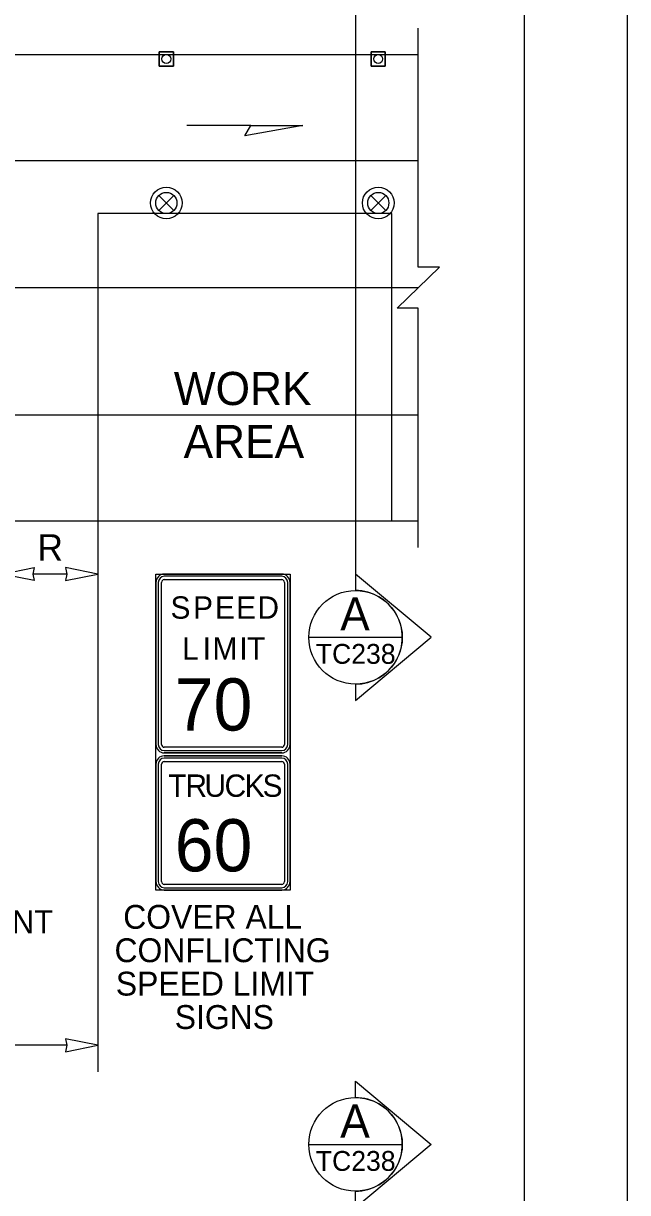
# Model space of a CAD drawing. Extents: x 99999 to 100116, y 99995 to 100013.
# Drawn here: x 100054.238 to 100056.062, y 100004.763 to 100008.293 of the extents above; entities that cross this region are included whole.
import ezdxf

# ---------------------------------------------------------------- set-up
doc = ezdxf.new("R2010")
doc.units = 0
for name, color, linetype in [('Default', 7, 'Continuous'), ('RD_MK_LineEdgeYellow', 7, 'Continuous'), ('RD_MK_LineLane', 7, 'Continuous'), ('SH_GI_PlotLimits', 7, 'Continuous'), ('SH_GI_SheetBorder', 7, 'Continuous'), ('SH_TI_WZSectionCut', 7, 'Continuous'), ('TR_SN_ConstructionSigns', 7, 'Continuous'), ('TR_WZ_TrafficCone', 7, 'Continuous'), ('TR_WZ_TrafficSafetyDrum', 7, 'Continuous'), ('TR_WZ_WorkAreaLabel', 7, 'Continuous'), ('TR_WZ_WorkZoneDetails', 7, 'Continuous'), ('TR_WZ_WorkZoneTextCurrent', 7, 'Continuous')]:
    doc.layers.add(name, color=color, linetype=linetype)

msp = doc.modelspace()

# ---------------------------------------------------------------- linework, layer by layer
at = {"layer": 'Default'}
for p, q in [((100055.0177, 100006.0819), (100054.6633, 100006.0819)), ((100054.638, 100006.0566), (100054.638, 100005.7022)), ((100055.043, 100005.7022), (100055.043, 100006.0566)), ((100054.6633, 100005.6769), (100055.0177, 100005.6769))]:
    msp.add_line(p, q, dxfattribs=at)
for centre, start, end in [((100054.6633, 100006.0566), 90, 180), ((100055.0177, 100006.0566), 0, 90), ((100054.6633, 100005.7022), 180, 270), ((100055.0177, 100005.7022), 270, 0)]:
    msp.add_arc(centre, 0.0253, start, end, dxfattribs=at)
at = {"layer": 'RD_MK_LineEdgeYellow'}
for p, q in [((100048.195, 100007.8789), (100055.43, 100007.8789)), ((100052.7368, 100007.1109), (100055.43, 100007.1109))]:
    msp.add_line(p, q, dxfattribs=at)
at = {"layer": 'RD_MK_LineLane'}
msp.add_lwpolyline([(100055.43, 100007.4949), (100048.195, 100007.4949)], dxfattribs=at)
at = {"layer": 'SH_GI_PlotLimits'}
msp.add_lwpolyline([(100039.0625, 99999.6875), (100056.0625, 99999.6875), (100056.0625, 100010.6875), (100039.0625, 100010.6875)], close=True, dxfattribs=at)
at = {"layer": 'SH_GI_SheetBorder'}
msp.add_line((100055.75, 100010.375), (100055.75, 100000), dxfattribs=at)
at = {"layer": 'SH_TI_WZSectionCut'}
for p, q in [((100055.2407, 100008.3589), (100055.2407, 100006.6309)), ((100055.2407, 100006.6309), (100055.2407, 100006.581)), ((100055.4689, 100006.4398), (100055.2407, 100006.6309)), ((100055.2407, 100006.2486), (100055.4689, 100006.4398)), ((100055.2407, 100006.2985), (100055.2407, 100006.2486)), ((100055.2407, 100005.0503), (100055.2407, 100005.1002)), ((100055.2407, 100005.1002), (100055.4688, 100004.9091)), ((100055.4688, 100004.9091), (100055.2407, 100004.718)), ((100055.2407, 100004.718), (100055.2407, 100004.7679))]:
    msp.add_line(p, q, dxfattribs=at)
for points in [[(100055.0995, 100006.4398), (100055.3819, 100006.4398)], [(100055.0995, 100004.9091), (100055.3819, 100004.9091)]]:
    msp.add_lwpolyline(points, dxfattribs=at)
for centre in [(100055.2407, 100006.4398), (100055.2407, 100004.9091)]:
    msp.add_circle(centre, 0.1412, dxfattribs=at)
for centre in [(100055.2407, 100006.4398), (100055.2407, 100004.9091)]:
    msp.add_arc(centre, 0.1412, 269.9978, 90.0022, dxfattribs=at)
at = {"layer": 'TR_SN_ConstructionSigns'}
for p, q in [((100054.638, 100006.1162), (100054.638, 100006.6056)), ((100054.638, 100006.6056), (100054.638, 100006.1162)), ((100054.6451, 100006.6056), (100054.6451, 100006.1162)), ((100054.6549, 100006.1162), (100054.6549, 100006.6056)), ((100054.6633, 100006.6309), (100055.0177, 100006.6309)), ((100055.0177, 100006.6309), (100054.6633, 100006.6309)), ((100055.0177, 100006.6239), (100054.6633, 100006.6239)), ((100054.6633, 100006.614), (100055.0177, 100006.614)), ((100055.0261, 100006.6056), (100055.0261, 100006.1162)), ((100055.036, 100006.1162), (100055.036, 100006.6056)), ((100055.043, 100006.6056), (100055.043, 100006.1162)), ((100055.043, 100006.1162), (100055.043, 100006.6056)), ((100055.0177, 100006.1078), (100054.6633, 100006.1078)), ((100054.6633, 100006.0979), (100055.0177, 100006.0979)), ((100055.0177, 100006.0909), (100054.6633, 100006.0909)), ((100054.6633, 100006.0909), (100055.0177, 100006.0909)), ((100054.6633, 100006.0819), (100055.0177, 100006.0819)), ((100055.0177, 100006.0819), (100054.6633, 100006.0819)), ((100055.0177, 100006.0749), (100054.6633, 100006.0749)), ((100054.638, 100005.7022), (100054.638, 100006.0566)), ((100054.638, 100006.0566), (100054.638, 100005.7022)), ((100054.6451, 100006.0566), (100054.6451, 100005.7022)), ((100054.6549, 100005.7022), (100054.6549, 100006.0566)), ((100054.6633, 100006.065), (100055.0177, 100006.065)), ((100055.0261, 100006.0566), (100055.0261, 100005.7022)), ((100055.036, 100005.7022), (100055.036, 100006.0566)), ((100055.043, 100006.0566), (100055.043, 100005.7022)), ((100055.043, 100005.7022), (100055.043, 100006.0566)), ((100055.0177, 100005.6938), (100054.6633, 100005.6938)), ((100054.6633, 100005.6839), (100055.0177, 100005.6839)), ((100055.0177, 100005.6769), (100054.6633, 100005.6769)), ((100054.6633, 100005.6769), (100055.0177, 100005.6769))]:
    msp.add_line(p, q, dxfattribs=at)
msp.add_lwpolyline([(100054.638, 100006.6309), (100055.043, 100006.6309), (100055.043, 100005.6769), (100054.638, 100005.6769)], close=True, dxfattribs=at)
for centre, radius, start, end in [((100054.6633, 100006.6056), 0.0253, 90, 180), ((100054.6633, 100006.6056), 0.0253, 90, 180), ((100054.6633, 100006.6056), 0.0183, 90, 180), ((100054.6633, 100006.6056), 0.00844, 90, 180), ((100055.0177, 100006.6056), 0.0253, 0, 90), ((100055.0177, 100006.6056), 0.0253, 360, 90), ((100055.0177, 100006.6056), 0.0183, 0, 90), ((100055.0177, 100006.6056), 0.00844, 360, 90), ((100054.6633, 100006.1162), 0.0253, 180, 270), ((100054.6633, 100006.1162), 0.0253, 180, 270), ((100054.6633, 100006.1162), 0.0183, 180, 270), ((100054.6633, 100006.1162), 0.00844, 180, 270), ((100055.0177, 100006.1162), 0.0253, 270, 0), ((100055.0177, 100006.1162), 0.0183, 270, 360), ((100055.0177, 100006.1162), 0.00844, 270, 0), ((100055.0177, 100006.1162), 0.0253, 270, 0), ((100054.6633, 100006.0566), 0.0253, 90, 180), ((100054.6633, 100006.0566), 0.0253, 90, 180), ((100054.6633, 100006.0566), 0.0183, 90, 180), ((100055.0177, 100006.0566), 0.0253, 0, 90), ((100055.0177, 100006.0566), 0.0253, 360, 90), ((100055.0177, 100006.0566), 0.0183, 0, 90), ((100054.6633, 100006.0566), 0.00844, 90, 180), ((100055.0177, 100006.0566), 0.00844, 360, 90), ((100054.6633, 100005.7022), 0.0253, 180, 270), ((100054.6633, 100005.7022), 0.0253, 180, 270), ((100055.0177, 100005.7022), 0.0253, 270, 0), ((100055.0177, 100005.7022), 0.0253, 270, 0), ((100055.0177, 100005.7022), 0.0183, 270, 360), ((100055.0177, 100005.7022), 0.00844, 270, 0)]:
    msp.add_arc(centre, radius, start, end, dxfattribs=at)
for major_axis, ratio, start_param, end_param in [((-0.0183, 0), 0.999596, 0, 1.570796), ((0.00844, 0), 0.99908, 3.141593, 4.712389)]:
    msp.add_ellipse((100054.6633, 100005.7022), major_axis=major_axis, ratio=ratio, start_param=start_param, end_param=end_param, dxfattribs=at)
at = {"layer": 'TR_WZ_TrafficCone'}
for points in [[(100054.6481, 100008.2069), (100054.6907, 100008.2069), (100054.6907, 100008.1642), (100054.6481, 100008.1642), (100054.6481, 100008.2069)], [(100054.6481, 100008.1642), (100054.6907, 100008.1642), (100054.6907, 100008.2069), (100054.6481, 100008.2069), (100054.6481, 100008.1642)], [(100055.2881, 100008.2069), (100055.3307, 100008.2069), (100055.3307, 100008.1642), (100055.2881, 100008.1642), (100055.2881, 100008.2069)], [(100055.2881, 100008.1642), (100055.3307, 100008.1642), (100055.3307, 100008.2069), (100055.2881, 100008.2069), (100055.2881, 100008.1642)]]:
    msp.add_lwpolyline(points, dxfattribs=at)
for centre in [(100054.6694, 100008.1856), (100055.3094, 100008.1856)]:
    msp.add_circle(centre, 0.0133, dxfattribs=at)
at = {"layer": 'TR_WZ_TrafficSafetyDrum'}
for p, q in [((100054.6468, 100007.7735), (100054.692, 100007.7283)), ((100054.692, 100007.7735), (100054.6468, 100007.7283)), ((100055.2868, 100007.7735), (100055.332, 100007.7283)), ((100055.332, 100007.7735), (100055.2868, 100007.7283))]:
    msp.add_line(p, q, dxfattribs=at)
for centre, radius in [((100054.6694, 100007.7509), 0.048), ((100054.6694, 100007.7509), 0.048), ((100055.3094, 100007.7509), 0.048), ((100055.3094, 100007.7509), 0.048), ((100054.6694, 100007.7509), 0.032), ((100055.3094, 100007.7509), 0.032)]:
    msp.add_circle(centre, radius, dxfattribs=at)
at = {"layer": 'TR_WZ_WorkZoneDetails'}
for p, q in [((100048.195, 100008.1989), (100055.43, 100008.1989)), ((100054.9242, 100007.985), (100054.7313, 100007.985)), ((100052.7368, 100006.7909), (100055.43, 100006.7909)), ((100054.4628, 100006.7909), (100054.4628, 100005.1282)), ((100054.3691, 100006.6309), (100054.2662, 100006.6309)), ((100054.3691, 100006.6309), (100054.2662, 100006.6309)), ((100054.3691, 100005.2082), (100050.6962, 100005.2082))]:
    msp.add_line(p, q, dxfattribs=at)
msp.add_lwpolyline([(100055.43, 100006.7109), (100055.43, 100007.433), (100055.366, 100007.433), (100055.494, 100007.5569), (100055.43, 100007.5569), (100055.43, 100008.2789)], dxfattribs=at)
for points in [[(100055.0815, 100007.985), (100054.9064, 100007.9541), (100054.9242, 100007.985)], [(100054.4628, 100007.7189), (100054.4628, 100006.7909), (100055.35, 100006.7909), (100055.35, 100007.7189)], [(100054.1724, 100006.6309), (100054.2707, 100006.6502), (100054.2662, 100006.6309), (100054.2707, 100006.6116)], [(100054.4628, 100006.6309), (100054.3645, 100006.6502), (100054.3691, 100006.6309), (100054.3645, 100006.6116)], [(100054.4628, 100005.2082), (100054.3645, 100005.2275), (100054.3691, 100005.2082), (100054.3645, 100005.1889)]]:
    msp.add_lwpolyline(points, close=True, dxfattribs=at)

# ---------------------------------------------------------------- texts
at = {"layer": 'Default'}
for s, height, p in [('S', 0.0675, (100054.6819, 100006.4959)), ('P', 0.0675, (100054.7501, 100006.4959)), ('E', 0.0675, (100054.8162, 100006.4959)), ('E', 0.0675, (100054.8803, 100006.4959)), ('D', 0.0675, (100054.9445, 100006.4959)), ('L', 0.0675, (100054.717, 100006.3722)), ('I', 0.0675, (100054.7791, 100006.3722)), ('M', 0.0675, (100054.8088, 100006.3722)), ('I', 0.0675, (100054.8898, 100006.3722)), ('T', 0.0675, (100054.9134, 100006.3722)), ('70', 0.1575, (100054.6949, 100006.1584)), ('T', 0.0675, (100054.6751, 100005.9582)), ('R', 0.0675, (100054.7271, 100005.9582)), ('U', 0.0675, (100054.7845, 100005.9582)), ('C', 0.0675, (100054.8452, 100005.9582)), ('K', 0.0675, (100054.906, 100005.9582)), ('S', 0.0675, (100054.96, 100005.9582)), ('60', 0.1575, (100054.6948, 100005.7332))]:
    msp.add_text(s, height=height, dxfattribs=at).set_placement(p)
at = {"layer": 'SH_TI_WZSectionCut'}
for s, height, rotation, p in [('A', 0.1, 0.01, (100055.1945, 100006.4604)), ('TC238', 0.06, 360, (100055.1209, 100006.3598)), ('A', 0.1, 0.01, (100055.1945, 100004.9297)), ('TC238', 0.06, 360, (100055.1209, 100004.8291))]:
    msp.add_text(s, height=height, rotation=rotation, dxfattribs=at).set_placement(p)
at = {"layer": 'TR_SN_ConstructionSigns'}
for s, p in [('COVER ALL', (100054.5392, 100005.5599)), ('CONFLICTING', (100054.5128, 100005.4591)), ('SPEED LIMIT', (100054.5168, 100005.3583)), ('SIGNS', (100054.6947, 100005.2575))]:
    msp.add_text(s, height=0.072, dxfattribs=at).set_placement(p)
at = {"layer": 'TR_WZ_WorkAreaLabel'}
for s, p in [('WORK', (100054.6919, 100007.1409)), ('AREA', (100054.7215, 100006.9809))]:
    msp.add_text(s, height=0.1, dxfattribs=at).set_placement(p)
at = {"layer": 'TR_WZ_WorkZoneDetails'}
msp.add_text('STRIPS PRESENT', height=0.07, dxfattribs=at).set_placement((100053.5214, 100005.546))
at = {"layer": 'TR_WZ_WorkZoneTextCurrent'}
msp.add_text('R', height=0.08, dxfattribs=at).set_placement((100054.28, 100006.6709))
msp.add_text('R', height=0.08, dxfattribs=at).set_placement((100054.28, 100006.6709))

doc.saveas('drawing.dxf')
